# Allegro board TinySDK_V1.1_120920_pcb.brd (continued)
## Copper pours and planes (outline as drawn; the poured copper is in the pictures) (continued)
GND on TOP (solid shape): 84.54,78.11 84.64,78.04 84.62,77.93 70.54,63.86 44.7,63.86 44.67,63.86 44.65,63.89 44.37,64.23 43.94,64.35 43.92,64.35 43.9,64.36 42.91,65.35 42.73,65.35 39.36,68.72 23.15,68.72 19.41,72.46 19.39,72.57 19.48,72.63 21.53,72.63 21.53,75.95 21.55,75.98 21.59,76 28.48,76 28.85,75.62 28.85,75.45 28.84,75.41 28.8,75.4 22.16,75.4 22.16,72.63 28.8,72.63 28.84,72.62 28.85,72.58 28.85,72.32 31.3,69.88 42.22,69.88 42.43,69.66 42.44,69.65 42.44,69.63 42.66,69.08 43.21,68.86 43.23,68.86 43.25,68.85 47.73,64.36 70.48,64.36 84.22,78.11
GND on TOP (solid shape): 61.06,81.94 61.1,81.99 61.15,81.98 61.18,81.94 61.22,81.9 61.23,81.89 61.23,81.87 61.23,80.56 62.23,80.56 62.36,80.43 62.37,80.41 62.58,80.03 62.99,79.88 63.68,79.88 63.72,79.87 63.73,79.83 63.73,79.37 64.77,79.37 64.81,79.36 64.82,79.32 64.82,78.16 66.47,78.16 66.51,78.14 66.52,78.1 66.52,76.85 65.89,76.23 64.06,76.23 64.02,76.24 64.01,76.28 64.01,76.58 63.96,76.58 63.92,76.6 63.91,76.63 63.91,77.68 63.92,77.72 63.96,77.73 64.25,77.73 64.25,79.21 61.23,79.21 61.23,79 61.2,78.95 61.14,78.96 61.11,79 61.08,79.03 61.07,79.04 61.06,79.07 61.06,79.32 61.08,79.36 61.11,79.37 61.75,79.37 61.75,80.39 61.11,80.39 61.08,80.41 61.06,80.44
GND on TOP (solid shape): 20.7,88.81 20.7,85.6 21.1,84.73 22.01,84.47 22.04,84.47 22.05,84.45 22.08,84.43 22.51,84.43 22.55,84.41 22.56,84.38 22.56,83.01 22.5,82.92 22.39,82.94 18.9,86.43 18.9,86.65 18.9,86.67 18.92,86.69 18.9,88.58 17.17,87.83 17.1,87.75 17,87.77 15.33,89.45 15.31,89.5 15.36,89.53 19.97,89.53
GND on TOP (solid shape): 47.92,46.88 48,46.82 48,46.72 48.01,45.97 48.67,45.62 48.69,45.62 48.71,45.6 48.97,45.34 48.99,45.34 49.08,45.3 49.09,45.2 49.19,44.52 49.81,44.22 49.84,44.21 50.22,43.84 59.63,43.84 59.71,43.8 59.73,43.72 59.72,43.56 59.73,43.4 59.71,43.32 59.63,43.28 29.54,43.28 28.62,44.2 28.6,44.31 28.69,44.37 28.77,44.37 28.8,44.36 29.34,44.12 29.88,44.36 29.9,44.37 29.92,44.37 38.98,44.37 41.48,46.88
GND on TOP (solid shape): 56.48,94.73 56.55,94.83 56.66,94.81 57.19,94.28 57.19,88.29 57.17,88.25 57.14,88.24 51.24,88.24 49.61,86.61 43.13,86.61 41.96,85.44 41.96,84.65 41.95,84.61 41.91,84.6 41.33,84.6 41.33,84.61 41.16,84.79 41.16,85.81 42.36,87.02 48.46,87.02 51.25,89.81 52.16,89.81 52.19,89.8 52.21,89.76 52.21,88.96 55.49,88.96 55.49,89.26 55.55,89.36 55.65,89.34 56.7,89.42 56.61,90.47 56.57,90.54 56.61,90.62 56.7,91.66 55.65,91.74 55.55,91.73 55.49,91.82 55.49,92.43 56.48,93.43
GND on TOP (solid shape): 178.81,35.81 178.92,35.83 178.98,35.74 178.98,33.19 178.92,33.09 178.81,33.12 177.04,32.44 178.81,31.75 178.92,31.78 178.98,31.69 178.98,26.52 178.95,26.47 178.9,26.48 178.88,26.5 178.88,29.07 177.89,29.07 177.01,29.95 176.93,29.95 176.84,30.02 176.87,30.13 177.11,31.48 175.78,31.84 175.68,31.84 175.63,31.93 175.63,32.95 175.68,33.03 175.78,33.04 176.89,33.14 177.24,34.2 177.24,34.22 177.25,34.25
GND on TOP (solid shape): 27.11,89.56 36.56,89.56 36.66,89.5 36.63,89.39 34.57,87.32 34.57,86.69 33.16,85.28 33.16,84.65 33.15,84.61 33.11,84.6 32.16,84.6 32.16,81.81 32.15,81.78 32.11,81.76 29.58,81.76 29.55,81.78 29.53,81.81 29.53,84.6 28.58,84.6 28.55,84.61 28.53,84.65 28.53,85.55 28.54,85.57 28.55,85.59 28.39,86.78 27.32,86.25 27.3,86.22 26.78,86.04 26.52,85.59 26.5,85.56 26.47,85.55 26.36,85.54 26.26,85.52 26.17,85.53 26.13,85.61 26.13,86.29 26.14,86.31 26.15,86.33 25.64,87.6 25.15,86.32 25.16,86.31 25.17,86.29 25.17,84.65 25.15,84.61 25.11,84.6 23.96,84.6 23.92,84.61 23.91,84.65 23.91,84.98 23.13,85.75 23.04,85.75 23,85.77 22.99,85.8 22.99,89.75 21.58,91.16 21.55,91.28 21.65,91.34 25.33,91.34
GND on TOP (solid shape): 127.4,30.53 127.45,30.47 127.71,30.14 128.1,30 128.13,29.98 128.14,29.95 128.14,28.17 128.08,28.08 127.97,28.1 123.12,26 127.97,23.9 128.08,23.92 128.14,23.83 128.14,21.87 128.1,21.79 128.01,21.78 127.08,21.36 127.45,20.41 127.47,20.39 127.48,20.37 127.48,19.72 127.47,19.69 127.43,19.67 127.32,19.67 127.32,19.66 127.29,19.63 125.78,19.63 125.78,19.17 125.72,19.07 125.61,19.09 122.91,21.79 122.91,27.87 125.42,30.38 126.95,30.38 127.06,30.49 127.08,30.5 127.1,30.51 127.22,30.51 127.33,30.53
GND on TOP (solid shape): 164.74,33.58 164.74,31.93 166.58,30.09 168.68,30.09 168.71,30.07 168.71,30.05 168.74,29.92 168.78,29.81 168.78,29.12 168.77,29.09 168.73,29.07 168.63,29.06 168.54,29.02 168.51,29.02 168.26,29.07 168.01,29.02 167.76,29.07 167.51,29.02 167.26,29.07 167.01,29.02 166.76,29.07 166.51,29.02 166.26,29.07 166.01,29.02 165.76,29.07 165.51,29.02 165.49,29.02 165.34,29.07 165.19,29.07 165.18,29.07 165.16,29.07 164.93,29.3 164.78,29.4 164.59,29.44 164.3,29.44 164.22,29.47 164.2,29.56 164.2,29.71 164.15,29.86 164.14,29.89 164.2,30.14 164.14,30.39 164.2,30.64 164.14,30.89 164.2,31.13 164.14,31.39 164.2,31.64 164.14,31.89 164.2,32.13 164.14,32.38 164.2,32.64 164.14,32.88 164.2,33.13 164.14,33.38 164.15,33.41 164.19,33.5 164.2,33.6 164.22,33.64 164.25,33.65 164.67,33.65
GND on TOP (solid shape): outline of 136 points within 29.89,66.9 120.47,93.95
GND on TOP (solid shape): 81.54,107.8 81.57,107.78 81.59,107.74 81.59,106.9 81.56,106.87 81.55,106.87 81.55,105.22 84.58,105.22 84.62,105.2 84.64,105.17 84.64,104.19 86.14,104.19 86.17,104.16 86.17,104.15 87.21,104.15 87.25,104.14 87.26,104.1 87.26,103.97 87.04,103.74 86.04,103.74 86.04,100.47 87.04,100.47 87.11,100.39 87.11,100.3 87.1,100.27 87.06,100.25 85.59,100.25 83.77,98.43 83.77,96.26 84.76,95.27 84.78,95.16 84.68,95.1 84.26,95.1 81.49,92.33 77.86,92.33 77.83,92.34 77.81,92.38 77.81,92.7 76.82,92.7 74.2,95.32 74.17,95.4 74.21,95.47 74.61,96.38 74.05,97.19 73.99,97.28 74.05,97.38 74.31,99 72.69,98.74 72.59,98.68 71.59,99.3 70.59,98.68 69.59,99.3 68.59,98.68 67.59,99.3 66.59,98.68 65.59,99.3 64.59,98.68 63.59,99.3 62.59,98.68 61.59,99.3 60.59,98.68 59.59,99.3 58.59,98.68 57.59,99.3 56.59,98.68 56.5,98.74 56.01,99.21 55.32,99.26 55.23,99.28 55.19,99.36 55.19,100.29 61.58,106.68 78.59,106.68 78.76,106.69 78.92,106.74 81.02,106.74 81.02,107.73 81.08,107.8
GND on TOP (solid shape): outline of 701 points within 127.75,48.89 178.98,128.98
GND on BOTTOM (solid shape): 23.5,32.17 23.56,32.27 23.67,32.25 24.55,31.37 56.18,31.37 56.27,31.31 56.25,31.2 56.04,30.99 32.67,30.99 30.9,29.21 27,29.21 26.87,29.08 25.24,29.08 23.5,30.83
GND on BOTTOM (solid shape): 149.16,78.24 149.2,78.22 149.21,78.19 149.21,77.51 148.23,76.53 148.23,72.43 147.86,72.06 147.75,72.03 147.69,72.13 147.69,73.34 147.37,73.34 147.33,73.36 147.32,73.39 147.32,76.53 149.02,78.24
GND on BOTTOM (solid shape): 148.5,59.12 149.16,59.12 149.2,59.11 149.21,59.07 149.21,58.83 149.2,58.79 149.16,58.78 146.89,58.78 146.79,58.84 146.81,58.95 146.88,59.02 146.88,60.59 146.9,60.63 146.93,60.64 146.98,60.64
GND on BOTTOM (solid shape): 149.16,61.66 149.2,61.65 149.21,61.61 149.21,61.29 151.19,61.29 151.23,61.28 151.24,61.24 151.24,60.51 151.23,60.47 151.19,60.45 149.21,60.45 149.21,60.14 149.2,60.1 149.16,60.09 148.9,60.09 147.69,61.3 147.69,61.61 147.7,61.65 147.74,61.66
GND on BOTTOM (solid shape): 9.24,37.77 9.35,37.79 9.42,37.7 9.42,37.28 7.47,35.33 6.98,35.33 6.96,35.34 6.94,35.36 6.8,35.58 6.62,35.77 6.59,35.85 6.62,35.93 6.8,36.11 6.94,36.34 6.96,36.36 6.98,36.37 7.84,36.37
GND on BOTTOM (solid shape): 9.35,42.2 9.46,42.22 9.52,42.13 9.52,41.7 7.15,39.33 6.98,39.33 6.96,39.34 6.94,39.36 6.8,39.58 6.62,39.77 6.59,39.85 6.62,39.93 6.8,40.11 6.94,40.34 6.96,40.36 6.98,40.37 7.52,40.37
GND on BOTTOM (solid shape): 10.01,40.83 10.12,40.85 10.19,40.75 10.19,40.08 7.44,37.33 6.98,37.33 6.96,37.34 6.94,37.36 6.8,37.58 6.62,37.77 6.59,37.85 6.62,37.93 6.8,38.11 6.94,38.34 6.96,38.36 6.98,38.37 7.55,38.37
GND on BOTTOM (solid shape): 147.48,88.08 147.53,88 147.53,87.06 127.71,67.24 127.71,56.57 122.65,51.51 122.06,51.51 121.96,51.57 121.98,51.68 127.18,56.88 127.18,66.93 146.69,86.44 146.69,87.93 146.72,88.01 146.81,88.03 147.1,88.01 147.39,88.09
GND on BOTTOM (solid shape): 78.45,40.51 78.54,40.45 78.52,40.34 77.28,39.1 68.83,39.1 65.48,35.76 65.46,35.76 64.88,35.31 64.97,34.58 64.98,34.47 64.89,34.42 59.77,34.42 59.68,34.48 59.7,34.59 65.62,40.51
GND on BOTTOM (solid shape): 122.48,38.11 122.58,38.05 122.56,37.94 121.07,36.45 112.39,36.45 111.6,37.24 111.58,37.35 111.68,37.41 120.17,37.41 120.19,37.39 120.2,37.38 121.2,36.92 121.54,37.96 121.54,38.06 121.63,38.11
GND on BOTTOM (solid shape): 144.4,67.97 144.43,67.96 144.45,67.92 144.45,67.28 144.42,67.25 144.41,67.25 144.41,65.72 144.37,65.64 144.29,65.62 143.46,65.17 143.76,64.27 143.81,64.19 143.78,64.11 139.29,59.62 139.18,59.6 139.12,59.69 139.12,61.9 142.38,65.16 142.38,67.79 142.57,67.97
GND on BOTTOM (solid shape): 105.05,52.21 105.08,52.22 105.1,52.2 106.12,51.18 106.12,50.74 106.12,50.72 106.1,50.71 106.01,50.6 105.94,50.49 105.87,50.43 105.78,50.45 105.49,50.62 105.15,50.64 105.07,50.66 105.03,50.74 105.03,50.77 105.04,50.79 105.05,50.8 105.31,51.4 104.98,51.97 104.93,52.05 104.96,52.13 105.02,52.18 105.03,52.21
GND on BOTTOM (solid shape): 4.35,51.22 4.46,51.22 4.51,51.14 4.51,50.62 7.52,47.61 7.52,46.17 7.51,46.15 7.32,45.87 7.26,45.54 7.25,45.52 7.06,45.33 6.97,45.33 6.94,45.35 6.94,45.36 6.8,45.58 6.62,45.77 6.59,45.85 6.62,45.93 6.98,47.26 5.84,48.06 4.81,48.06 4.32,48.55 4.32,51.17 4.32,51.2
GND on BOTTOM (solid shape): 105.81,103.12 106.13,103.12 106.23,103.06 106.21,102.95 106.15,102.89 106.15,95.2 106.23,94.42 106.96,94.15 107.05,94.13 107.09,94.05 107.09,85.33 110.77,81.65 110.77,66.25 118.28,58.75 118.29,58.71 118.28,58.68 118.24,58.64 118.21,58.59 118.19,58.58 118.16,58.57 117.58,58.57 110.41,65.74 110.41,80.75 105.73,85.44 105.73,96.38 105.22,96.88 105.22,102.53 105.35,102.78 105.38,103.05 105.42,103.14 105.5,103.16
GND on BOTTOM (solid shape): 171.26,41.17 171.32,41.27 171.43,41.25 171.55,41.13 171.55,38.21 173.04,36.72 173.04,36.71 173.2,36.45 173.45,36.28 173.47,36.26 173.48,36.23 173.48,30.5 173.25,30.26 173.24,30.26 172.79,29.82 172.84,29.2 172.84,29.11 172.76,29.05 172.59,29.01 172.43,28.93 170.71,28.93 170.62,28.97 170.61,29.07 170.66,29.32 170.63,29.57 170.62,29.58 170.62,30.66 170.63,30.66 170.63,31.61 170.62,31.61 170.62,33.2 171.26,33.84
GND on BOTTOM (solid shape): 93.41,121.81 96.31,118.9 102.36,118.9 105.19,116.08 108.22,116.08 108.84,116.08 112.55,112.37 112.55,112.33 112.53,112.3 112.29,111.76 112.53,111.22 112.54,111.2 112.55,111.18 112.55,103.7 110.08,101.24 110.08,97.53 110.13,97.48 110.13,97.34 110.08,97.28 110.08,86.97 113.74,83.32 113.74,68.58 118.04,64.28 118.04,64.26 118.04,64.24 118.01,63.97 118.06,63.7 118.04,63.61 117.96,63.57 117.66,63.57 113.36,67.87 113.36,82.65 109.63,86.38 109.63,101.72 111.73,103.83 111.73,110.42 111.74,110.44 111.75,110.46 111.99,111 111.75,111.54 111.74,111.56 111.73,111.58 111.73,111.83 107.67,115.9 105.11,115.9 102.29,118.73 95.7,118.73 93.15,121.27 93.15,121.62 93.16,121.65 93.18,121.67 93.27,121.73 93.35,121.8 93.37,121.81
GND on BOTTOM (solid shape): 101.8,64.89 101.85,64.8 101.85,61.91 101.82,61.83 101.73,61.81 101.65,61.82 101.54,61.83 100.85,62.52 100.45,62.52 99.92,63.05 96.97,63.05 95.73,64.29 95.7,64.39 95.79,64.46 96.02,64.54 96.22,64.69 96.24,64.7 96.26,64.71 97.17,64.71 98.61,63.27 99.96,63.27 99.99,63.27 100,63.25 100.91,63.07 101.28,63.92 101.28,63.95 101.58,64.33 101.59,64.79 101.59,64.82 101.62,64.85 101.66,64.87 101.7,64.89
GND on BOTTOM (solid shape): 81.01,40.96 81.1,40.89 81.08,40.78 76.66,36.36 76.54,36.34 76.48,36.45 74.82,37.27 75.64,35.61 75.75,35.55 75.73,35.43 74.71,34.42 66.22,34.42 66.13,34.47 66.14,34.58 66.24,34.75 66.29,34.93 66.29,34.95 69.3,37.96 77.76,37.96 80.75,40.96
GND on BOTTOM (solid shape): 144.24,62.63 144.35,62.65 144.41,62.56 144.41,62.18 144.4,62.14 144.36,62.13 144,62.13 143.91,62.04 143.9,62.04 143.45,61.1 144.37,60.64 144.38,60.64 145.86,60.64 145.9,60.63 145.91,60.59 145.91,59.42 143.71,57.21 143.6,57.19 143.54,57.28 143.54,58.4 143.91,58.77 143.94,58.78 143.97,58.77 145.13,59.32 144.06,60.03 143.98,60.02 143.92,60.07 143.47,60.47 142.87,60.4 142.84,60.39 142.81,60.41 142.65,60.55 142.46,60.65 142.4,60.72 142.42,60.81
GND on BOTTOM (solid shape): outline of 219 points within 80.69,42.1 106.63,59.66
(no net) on TOP: 4,1.02 1.89,1.89 1.02,4 1.02,126 1.89,128.11 4,128.98 176,128.98 178.11,128.11 178.98,126 178.98,4 178.11,1.89 176,1.02 150.11,1.02 148.97,2.16 148.97,18.92 152.65,22.61 152.65,36.58 151.51,37.72 143.76,37.72 142.11,36.07 142.11,33.27 141.6,32.77 139.19,32.77 138.94,33.02 138.94,38.61 136.27,38.61 135.13,37.47 130.81,37.47 130.81,37.34 130.43,36.96 130.43,34.29 128.14,32 128.14,15.37 129.16,14.35 129.16,1.02 ; 1 cut-out
(no net) on BOTTOM: 4,1.02 1.89,1.89 1.02,4 1.02,126 1.89,128.11 4,128.98 176,128.98 178.11,128.11 178.98,126 178.98,4 178.11,1.89 176,1.02 150.11,1.02 148.97,2.16 148.97,18.92 152.65,22.61 152.65,36.58 151.51,37.72 143.76,37.72 142.11,36.07 142.11,33.27 141.6,32.77 139.19,32.77 138.94,33.02 138.94,38.61 136.27,38.61 135.13,37.47 130.45,37.47 130.45,37.41 129.44,36.4 129.44,34.82 129.79,34.47 129.79,34.09 128.14,32.44 128.14,15.37 129.16,14.35 129.16,1.02
CCD_AGND on BOTTOM: 153.8,101.73 153.8,105.54 154.18,105.92 157.73,105.92 160.78,108.97 163.32,108.97 164.72,110.36 164.72,111.38 167.26,113.92 171.96,113.92 172.59,113.28 172.59,98.04 169.04,94.49 162.94,94.49 157.48,99.95 151,99.95 150.5,100.46 150.5,100.97 150.75,101.22 153.29,101.22

Small or netless copper shapes (teardrops, artwork), in the pictures only: 46 on TOP, 16 on BOTTOM

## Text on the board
Ref Des/Silkscreen Top: EINT26 | EINT25 | EINT24 | EINT19 | EINT18 | EINT17 | EINT16 | EINT27 | VIN | GND | 5V | (UARTS) | CCD | CMOS | VCLK | SDA2 | SCL2 | 3.3V | AIN0 | AIN1 | AIN6 | AIN7 | AIN8 | AIN9 | NAND | SDBOOT | A | B | ON | OFF | TinySDK V1.1 120920
DIMENSION: FIGURE | SIZE | 14.0 | 27.559 | 27.56 | 28.0 | 31.0 | 31.496 | 31.5 | 35.429 | 39.0 | 39.37 | 40.0 | 43.311 | 45.0 | 47.0 | 50.0 | 60.0 | 62.988 | 70.0 | 78.74 | 80.0 | 82.681 | 87.0 | 98.0 | 118.11 | 125.98 | 126.0 | 35.0 | 43.0 | 63.0 | 71.0 | 100.0 | 137.799 | 48.0x40.0 | DRILL CHART: TOP to BOTTOM | ALL UNITS ARE IN MILS | TOLERANCE | +0.0/-0.0 | +3.0/-3.0 | +2.988/-2.988 | +2.0/-0.0 | PLATED | NON-PLATED | QTY | 1274 | 81 | 2 | 1 | 6 | 150 | 27 | 3 | 31 | 7 | 17 | 4 | 18 | 10 | 14
